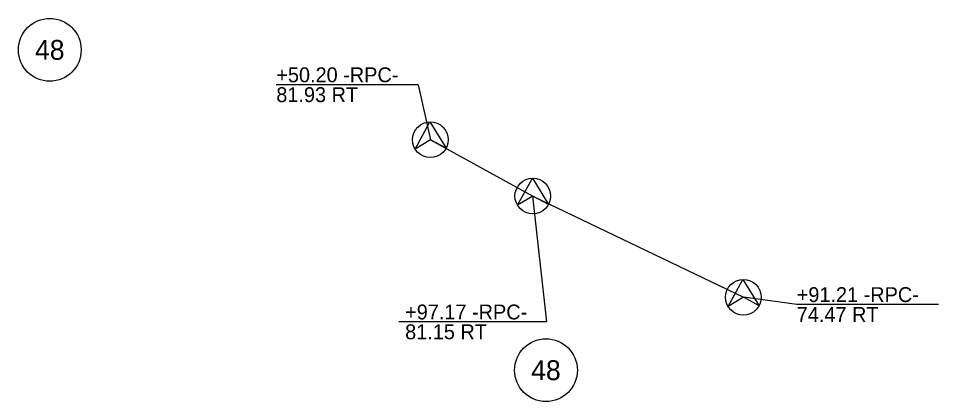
# Model space of a CAD drawing. Extents: x 1638966 to 1642158, y 841755 to 844938.
# Drawn here: x 1640551.2 to 1640922.6, y 842146.1 to 842300.5 of the extents above; entities that cross this region are included whole.
import ezdxf

# ---------------------------------------------------------------- set-up
doc = ezdxf.new("R2010")
doc.units = 0
for name, color, linetype in [('Exist Building', 7, 'Continuous'), ('Exist Guardrail Text', 7, 'Continuous'), ('Exist Structure Major Deck Tunnel Box Culvert Text', 7, 'Continuous'), ('Prop ROW Marker CELL', 7, 'Continuous')]:
    doc.layers.add(name, color=color, linetype=linetype)

msp = doc.modelspace()

# ---------------------------------------------------------------- linework, layer by layer
at = {"layer": 'Exist Building'}
for centre in [(1640563.88, 842287.86), (1640764.13, 842158.72)]:
    msp.add_circle(centre, 12.66, dxfattribs=at)
at = {"layer": 'Exist Guardrail Text'}
for p, q in [((1640712.54, 842273.79), (1640655.3, 842273.79)), ((1640712.54, 842273.79), (1640717.47, 842251.62)), ((1640764.53, 842178.18), (1640758.81, 842228.92)), ((1640865.33, 842185.18), (1640843.79, 842188.1)), ((1640922.57, 842185.18), (1640865.33, 842185.18)), ((1640764.53, 842178.18), (1640704.81, 842178.18))]:
    msp.add_line(p, q, dxfattribs=at)
at = {"layer": 'Exist Structure Major Deck Tunnel Box Culvert Text'}
for p, q in [((1640717.47, 842251.62), (1640758.81, 842228.92)), ((1640758.81, 842228.92), (1640843.79, 842188.1))]:
    msp.add_line(p, q, dxfattribs=at)
at = {"layer": 'Prop ROW Marker CELL'}
for p, q in [((1640711.31, 842247.88), (1640717.3, 842258.82)), ((1640717.3, 842258.82), (1640723.81, 842248.17)), ((1640717.47, 842251.62), (1640711.31, 842247.88)), ((1640723.81, 842248.17), (1640717.47, 842251.62)), ((1640752.65, 842225.18), (1640758.64, 842236.12)), ((1640758.64, 842236.12), (1640765.15, 842225.47)), ((1640758.81, 842228.92), (1640752.65, 842225.18)), ((1640765.15, 842225.47), (1640758.81, 842228.92)), ((1640837.62, 842184.35), (1640843.62, 842195.3)), ((1640843.62, 842195.3), (1640850.12, 842184.65)), ((1640843.79, 842188.1), (1640837.62, 842184.35)), ((1640850.12, 842184.65), (1640843.79, 842188.1))]:
    msp.add_line(p, q, dxfattribs=at)
for centre in [(1640717.47, 842251.62), (1640758.81, 842228.92), (1640843.79, 842188.1)]:
    msp.add_circle(centre, 7.2, dxfattribs=at)

# ---------------------------------------------------------------- texts
at = {"layer": 'Exist Building'}
for p in [(1640557.92, 842283.86), (1640758.17, 842154.72)]:
    msp.add_text('48', height=8, rotation=360, dxfattribs=at).set_placement(p)
at = {"layer": 'Exist Guardrail Text'}
for s, p in [('+50.20 -RPC-', (1640655.3, 842274.79)), ('81.93 RT', (1640655.3, 842266.79)), ('+91.21 -RPC-', (1640865.33, 842186.18)), ('+97.17 -RPC-', (1640707.29, 842179.18)), ('74.47 RT', (1640865.33, 842178.18)), ('81.15 RT', (1640707.29, 842171.18))]:
    msp.add_text(s, height=6, dxfattribs=at).set_placement(p)

doc.saveas('drawing.dxf')
